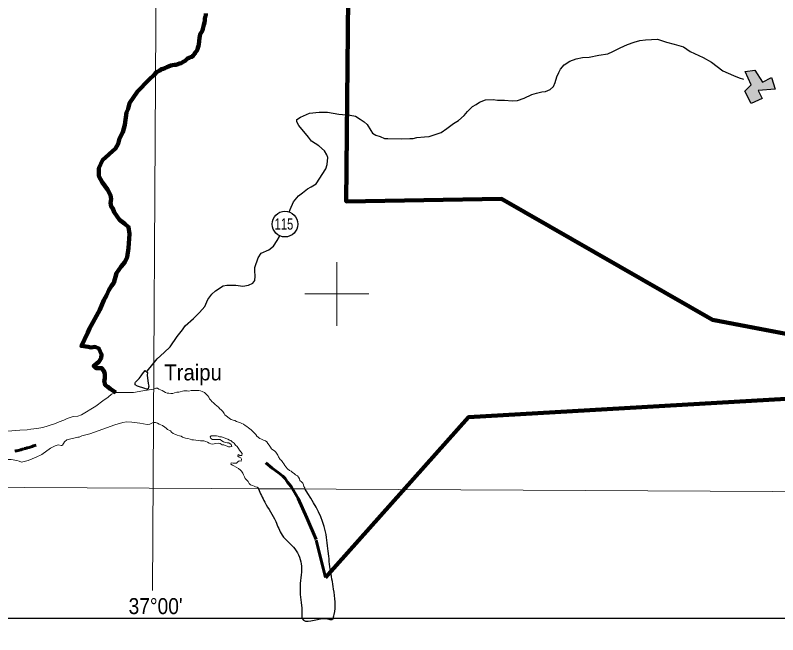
# Model space of a CAD drawing. Extents: x -1643653 to 4543381, y 1624270 to 13878484.
# Drawn here: x 714916 to 738822, y 8889327 to 8908730 of the extents above; entities that cross this region are included whole.
import ezdxf
from ezdxf.enums import TextEntityAlignment as Align

# ---------------------------------------------------------------- set-up
doc = ezdxf.new("R2010")
doc.units = 0
doc.header["$LTSCALE"] = 200
doc.linetypes.add('LONG_DASH_SHORT_DASH', pattern=[9.9, 6, -1.2, 1.5, -1.2])
for name, color, linetype, lineweight in [('1', 7, 'Continuous', 13), ('12', 7, 'Continuous', 25), ('2', 7, 'Continuous', 13), ('21', 7, 'Continuous', 25), ('24', 7, 'Continuous', 25), ('25', 7, 'Continuous', 13), ('3', 7, 'Continuous', 13), ('48', 7, 'Continuous', 25), ('53', 7, 'Continuous', 106), ('60', 7, 'Continuous', 13), ('7', 7, 'LONG_DASH_SHORT_DASH', 60), ('9', 7, 'Continuous', 90)]:
    doc.layers.add(name, color=color, linetype=linetype, lineweight=lineweight)
doc.layers.add('41', color=7, linetype='Continuous')
doc.layers.add('46', color=7, linetype='Continuous')

msp = doc.modelspace()

# ---------------------------------------------------------------- hatches: boundary and pattern name
at = {"layer": '21'}
msp.add_hatch(color=256, dxfattribs=at).paths.add_polyline_path([(737801.5, 8906970.9), (738106.6, 8907012.5), (738347.6, 8906633.5), (738630.7, 8906778.2), (738745.6, 8906416), (738212.5, 8906368.9), (738331.1, 8906121.9), (737984.3, 8905966.4), (737794.3, 8906356.6), (737990.6, 8906555.2)])

# ---------------------------------------------------------------- linework, layer by layer
at = {"layer": '1'}
for points in [[(719978.9, 9023574.5), (719561.6, 8949232.2), (719215.6, 8890710.6)], [(564751.7, 8894587.5), (664411.9, 8894209.9), (791388.5, 8893536.2)]]:
    msp.add_lwpolyline(points, dxfattribs=at)
at = {"layer": '12'}
for points in [[(732698.6, 8907406), (732912.6, 8907415.8), (733208.3, 8907476.3), (733493.7, 8907526.8), (733646.8, 8907597.8), (733881.6, 8907714.5), (734106.1, 8907810.9), (734320.4, 8907892), (734498.8, 8907937.5), (734677.2, 8907962.7), (734865.7, 8907967.4), (735054.3, 8907977.3), (735334.1, 8907885.1), (735578.4, 8907823.5), (735863.4, 8907741.4), (736076.8, 8907598.4), (736483.7, 8907404.1), (736742.9, 8907255.9), (737103.6, 8906990.3), (737439.3, 8906842), (737612.3, 8906775.4), (737750.2, 8906727.3)], [(727039.6, 8904864.2), (727284.1, 8904868.9), (727391.1, 8904868.7), (727508.4, 8904899), (727747.9, 8904919), (727890.6, 8904928.9), (728048.7, 8904984.6), (728268, 8905055.5), (728451.9, 8905187.7), (728651.2, 8905340.1), (728809.4, 8905436.6), (728993.4, 8905594.2), (729095.8, 8905716.2), (729249.1, 8905868.8), (729371.7, 8905934.8), (729473.8, 8906011), (729657.5, 8906082), (729896.9, 8906091.7), (730039.5, 8906071.1), (730253.5, 8906065.6), (730497.9, 8906055), (730661, 8906064.9), (730870.1, 8906130.7), (731110, 8906247.4), (731263, 8906293), (731426.1, 8906328.3), (731543.3, 8906338.3), (731686.2, 8906409.4), (731788.5, 8906500.9), (731839.8, 8906623.1), (731891.5, 8906806.3), (731958.2, 8906938.7), (732014.6, 8907040.4), (732122.1, 8907172.7), (732300.8, 8907289.5), (732499.7, 8907365.6), (732698.6, 8907406)], [(723502.8, 8902567), (723531.6, 8902649.7), (723639.5, 8902883.8), (723793, 8903072), (723920.7, 8903168.5), (724079.1, 8903290.5), (724191.4, 8903356.5), (724349.7, 8903453), (724652, 8903916), (724698.3, 8904058.6), (724714.4, 8904272.5), (724689.2, 8904354.1), (724613.3, 8904481.5), (724430.5, 8904644.9), (724201.8, 8904787.9), (724110.5, 8904915.5), (723811.3, 8905272.6), (723745.5, 8905389.9), (723740.7, 8905461.2), (723858.1, 8905542.5), (724143.8, 8905659.1), (724444.6, 8905699.3), (724704.4, 8905698.9), (725060.7, 8905637.1), (725417.2, 8905595.7), (725585.2, 8905564.8), (725732.6, 8905477.9), (725859.7, 8905396.2), (725945.9, 8905304.3), (726062.4, 8905115.6), (726113.1, 8905039.1), (726219.8, 8904977.8), (726352.1, 8904931.7), (726489.4, 8904870.3), (726601.5, 8904865), (727039.6, 8904864.2)], [(719051.7, 8897586.9), (719362.5, 8897965.7), (719587.4, 8898163.9), (719771.5, 8898341.9), (719996.8, 8898667.5), (720160.6, 8898881.1), (720247.7, 8899003.2), (720508.3, 8899237.1), (720697.5, 8899420.1), (720856.1, 8899608.3), (720953.7, 8899827.2), (721076.6, 8899989.9), (721194.2, 8900101.8), (721434.2, 8900254.2), (721551.4, 8900279.4), (721826.5, 8900273.8), (722050.5, 8900248), (722223.9, 8900278.2), (722366.7, 8900339.1), (722428.2, 8900425.6), (722433.7, 8900552.9), (722424.2, 8900726.1), (722429.7, 8900828), (722532.7, 8901133.4), (722624.9, 8901275.9), (722864.7, 8901387.5), (723007.8, 8901494.2), (723130.7, 8901677.4), (723197.4, 8901799.6), (723209.3, 8901823.1)]]:
    msp.add_lwpolyline(points, dxfattribs=at)
at = {"layer": '2'}
for p, q in [((725000, 8899000), (725000, 8901000)), ((724000, 8900000), (726000, 8900000))]:
    msp.add_line(p, q, dxfattribs=at)
at = {"layer": '21'}
for points in [[(737801.5, 8906970.9), (738106.6, 8907012.5), (738347.6, 8906633.5), (738630.7, 8906778.2), (738745.6, 8906416), (738212.5, 8906368.9), (738331.1, 8906121.9), (737984.3, 8905966.4), (737794.3, 8906356.6), (737990.6, 8906555.2)], [(718993.1, 8897599.9), (719057.4, 8897544.6), (719055.9, 8897461.4), (719085.3, 8897192.5), (719103.1, 8897108.8), (719098.1, 8897076.1), (719079.4, 8897033), (719065.5, 8897020), (719028.2, 8897020.1), (718974.7, 8897034.1), (718746.2, 8897111.7), (718679.7, 8897153.1), (718671.6, 8897221.2), (718685, 8897240.1), (718799.2, 8897348.2), (718862.4, 8897430.9), (718906.6, 8897502.9)]]:
    msp.add_lwpolyline(points, close=True, dxfattribs=at)
at = {"layer": '24', "lineweight": 53}
for points in [[(720886.9, 8908780.4), (720886.5, 8908724.4), (720865.8, 8908678.7), (720860.4, 8908622.7), (720854.9, 8908561.6), (720844.3, 8908500.6), (720828.6, 8908434.4), (720818, 8908383.6), (720797.2, 8908307.3), (720781.6, 8908256.4), (720750.7, 8908200.6), (720714.6, 8908139.7), (720699, 8908078.7), (720693.5, 8908027.8), (720680.1, 8907917.9)], [(720680.1, 8907917.9), (720671.8, 8907819.1), (720661.2, 8907768.2), (720640.5, 8907712.3), (720624.9, 8907661.5), (720594, 8907605.6), (720558.1, 8907560), (720532.3, 8907509.3), (720496.4, 8907468.7), (720460.5, 8907428.2), (720409.6, 8907413.3), (720363.7, 8907393.2), (720312.7, 8907373.1), (720276.8, 8907337.7), (720241, 8907302.3), (720179.7, 8907267), (720118.4, 8907231.8), (720062.3, 8907216.8), (720016.4, 8907196.8), (719965.5, 8907181.8), (719909.5, 8907177.1), (719843.3, 8907162.2), (719792.3, 8907152.3), (719720.9, 8907122.2), (719664.9, 8907107.3), (719603.6, 8907077.1), (719552.6, 8907057.1), (719496.6, 8907042.2), (719445.4, 8907001.8), (719343.4, 8906951.5), (719283.6, 8906877)], [(719283.6, 8906877), (719100.8, 8906711), (718751.9, 8906345.6), (718502.7, 8905980.3), (718452.8, 8905797.7), (718403, 8905681.4), (718353.1, 8905299.5), (718286.7, 8905067), (718187, 8904867.8), (718137.2, 8904701.7), (718054.1, 8904552.2), (717859.9, 8904374.3), (717854.7, 8904369.6)], [(717854.7, 8904369.6), (717655.3, 8904186.9), (717539, 8903937.8), (717539, 8903688.8), (717638.7, 8903506.1), (717804.9, 8903273.6), (717904.6, 8903091), (717921.2, 8902974.7), (717904.6, 8902858.5), (717921.2, 8902742.3), (717971.1, 8902675.9), (718020.9, 8902559.6), (718187, 8902327.1), (718353.2, 8902194.3), (718469.5, 8902094.7), (718502.7, 8901878.8), (718469.5, 8901430.4), (718419.6, 8901148.2), (718353.2, 8900998.7), (718236.8, 8900865.9), (718087.3, 8900650), (718004.2, 8900351.1), (717937.8, 8900251.5), (717854.7, 8900118.6), (717771.7, 8899952.6), (717688.6, 8899803.1), (717572.3, 8899504.2), (717240, 8898923), (717190.1, 8898790.2), (717090.4, 8898574.3), (716990.8, 8898375.1), (717206.8, 8898341.9), (717289.8, 8898325.2), (717422.7, 8898341.9), (717539, 8898292), (717622.1, 8898109.4), (717605.5, 8897993.1), (717539, 8897876.9), (717472.6, 8897827.1), (717422.7, 8897777.3), (717372.9, 8897744.1), (717439.4, 8897677.6), (717622.1, 8897677.6), (717688.6, 8897594.6), (717721.8, 8897495), (717721.8, 8897395.3), (717721.8, 8897345.5), (717705.2, 8897279.1), (717721.8, 8897196.1), (717738.4, 8897146.3), (717821.5, 8897096.4), (717888, 8897030), (718070.7, 8896913.8)]]:
    msp.add_lwpolyline(points, dxfattribs=at)
at = {"layer": '25', "lineweight": 25}
msp.add_line((724002.8, 8893886.5), (722537.3, 8893896.5), dxfattribs=at)
msp.add_line((724002.8, 8893886.5), (722537.3, 8893896.5), dxfattribs=at)
at = {"layer": '25'}
for points in [[(716671.9, 8896141.4), (716736, 8896160), (716876.8, 8896172.9), (716996.8, 8896216.3), (717443.2, 8896481.3), (717658.9, 8896651.8), (717833.2, 8896772.8), (717934, 8896865.6), (718070.7, 8896913.8), (718220.3, 8896913.8), (718619, 8896913.8), (718918.1, 8896963.6), (719252.2, 8897020.3)], [(719252.2, 8897020.3), (719320.1, 8897049.2), (719376, 8897048.8), (719416.5, 8897018), (719467.2, 8896997.3), (719517.9, 8896971.5), (719578.7, 8896940.5), (719624.3, 8896914.8), (719680.1, 8896894), (719736.1, 8896888.6), (719797.1, 8896883.1), (719858.1, 8896887.8), (719909.1, 8896907.8), (719980.4, 8896922.7), (720046.6, 8896927.3), (720199.4, 8896962), (720255.3, 8896961.7), (720306.2, 8896961.3), (720362.2, 8896961), (720428.4, 8896980.9), (720479.3, 8896980.6), (720540.3, 8896980.2), (720606.4, 8896979.8), (720667.5, 8896979.4), (720723.3, 8896968.8), (720779.1, 8896948.1), (720845, 8896917.1), (720880.4, 8896881.2), (720920.8, 8896845.3), (720956.2, 8896809.4)], [(720956.2, 8896809.4), (720981.3, 8896763.4), (721006.4, 8896717.4), (721046.8, 8896676.4), (721082.2, 8896635.4), (721127.7, 8896594.4), (721188.3, 8896538), (721289.5, 8896455.8), (721329.8, 8896404.6), (721375.3, 8896368.7), (721420.8, 8896322.5), (721461, 8896261.2), (721486.2, 8896215.2), (721567.1, 8896148.4), (721627.8, 8896097.1), (721683.5, 8896071.3), (721749.5, 8896050.5), (721805.3, 8896034.8), (721856, 8896009), (721916.9, 8895988.3), (721972.7, 8895967.5), (722018.4, 8895946.9), (722069, 8895921.1), (722119.7, 8895885.1), (722175.4, 8895854.2), (722231, 8895808), (722271.5, 8895772), (722312, 8895741.2), (722367.5, 8895689.9), (722402.9, 8895654), (722463.5, 8895597.6), (722493.7, 8895546.5), (722584.8, 8895474.6), (722635.5, 8895453.9), (722701.4, 8895417.8), (722762.3, 8895402.1), (722802.7, 8895366.2), (722832.9, 8895320.2), (722873.2, 8895263.9), (722923.6, 8895197.3), (722953.8, 8895151.3), (722994.3, 8895120.5), (723039.9, 8895089.6), (723085.4, 8895048.6), (723145.7, 8894951.4), (723165.7, 8894895.3), (723221.1, 8894818.5), (723261.6, 8894782.6), (723301.9, 8894726.3), (723337.1, 8894675.1), (723367.3, 8894624), (723402.6, 8894583), (723453.1, 8894526.7), (723518.8, 8894475.3), (723564.4, 8894449.5), (723609.9, 8894408.5), (723655.5, 8894372.5), (723706.1, 8894336.6), (723761.8, 8894305.6), (723797.1, 8894259.6), (723827.3, 8894208.4), (723842.2, 8894157.4), (723887.6, 8894111.3), (723928.1, 8894075.3), (723948, 8894019.2)], [(715944.9, 8895871), (716177.3, 8895944.3), (716297, 8895998.6), (716434.9, 8896046.3), (716544.4, 8896104.3), (716671.9, 8896141.4)], [(715407.8, 8895761.9), (715591.5, 8895783.2), (715777.5, 8895818.2), (715944.9, 8895871)], [(719242.1, 8895974.6), (719137.8, 8895926.7), (719051.9, 8895910.8), (718819, 8895950.7), (718570.6, 8895982.3), (718406.7, 8895992.1), (718284.1, 8895976.8), (718038.4, 8895905.8), (717250.7, 8895623.3), (716998.4, 8895554.6), (716915, 8895518.1), (716881.8, 8895513.8)], [(721516.7, 8895476.3), (721445.7, 8895507.4), (721379.7, 8895523.1), (721323.7, 8895523.4), (721273, 8895544.1), (721222.2, 8895559.7), (721151.1, 8895560.2), (721054.4, 8895560.8), (721023.6, 8895520.3), (721043.6, 8895469.2), (721104.5, 8895443.3), (721160.4, 8895443), (721211.3, 8895442.7), (721277.4, 8895442.2), (721343.5, 8895436.7), (721394.1, 8895395.6), (721444.7, 8895364.7), (721505.6, 8895344), (721561.5, 8895338.5), (721612.4, 8895338.2), (721688.3, 8895286.8), (721708.2, 8895225.5), (721657.3, 8895210.6), (721606.4, 8895210.9), (721555.7, 8895231.6), (721499.9, 8895252.3), (721454.2, 8895273), (721398.3, 8895278.4), (721342.7, 8895319.6), (721276.6, 8895325.1), (721205.3, 8895320.4), (721154.4, 8895305.5), (721098.4, 8895300.7), (721042.5, 8895301.1), (720996.9, 8895326.9), (720941.1, 8895357.8), (720890.4, 8895378.5), (720824.4, 8895399.3), (720773.6, 8895399.6), (720722.7, 8895399.9), (720656.6, 8895405.4), (720580.4, 8895421.2), (720509.3, 8895426.8), (720448.2, 8895427.2), (720397.5, 8895447.9), (720326.5, 8895468.7), (720250.3, 8895484.5), (720158.9, 8895515.6), (720113.3, 8895541.4), (720062.6, 8895557), (719996.6, 8895577.8), (719920.5, 8895608.8), (719864.8, 8895634.7), (719819.3, 8895675.7), (719778.8, 8895711.6), (719692.7, 8895758), (719647.2, 8895799.1), (719606.7, 8895829.9), (719535.8, 8895876.2), (719480.1, 8895902), (719429.3, 8895917.6), (719373.6, 8895948.5), (719317.8, 8895969.3), (719266.9, 8895969.6), (719242.1, 8895974.6)], [(714514.6, 8895674.6), (714664.7, 8895703.8), (714810.4, 8895708.8), (715055.3, 8895739.1), (715289.1, 8895748.2), (715407.8, 8895761.9)], [(716881.8, 8895513.8), (716841.2, 8895508.6), (716533, 8895427), (716458.2, 8895365.9), (716394.5, 8895260), (716374.9, 8895256.9)], [(722073.4, 8894336.8), (722053.4, 8894382.8), (722013.2, 8894449.3), (721972.7, 8894485.2), (721917.1, 8894531.4), (721846.2, 8894572.6), (721770.2, 8894618.9), (721724.6, 8894639.6), (721673.9, 8894665.4), (721689.5, 8894716.2), (721745.3, 8894700.6), (721801.3, 8894700.2), (721852.2, 8894705), (721893.1, 8894740.4), (721934, 8894770.7), (721995, 8894765.2), (722010.6, 8894821.2), (721985.5, 8894867.2), (721934.8, 8894893), (721889.3, 8894923.8), (721909.9, 8894969.5), (721960.6, 8894943.7), (722021.6, 8894943.3), (722027.1, 8895004.4), (721986.8, 8895050.5), (721946.5, 8895106.8), (721911.2, 8895163.1), (721871, 8895219.4), (721825.5, 8895260.4), (721780.1, 8895321.8), (721719.4, 8895368.1), (721679, 8895409.1), (721628.2, 8895424.7), (721577.6, 8895455.6), (721516.7, 8895476.3)], [(715039.1, 8894760), (714963.6, 8894786.5), (714790.6, 8894820), (714606.1, 8894818.8), (714473.2, 8894853.3), (714404.1, 8894859.6), (714116.9, 8894843.6), (714034.5, 8894876.8), (713967, 8894916.7), (713850.5, 8895013.2), (713789.1, 8895053.9), (713604, 8895144.8), (713532.7, 8895186.2)], [(716374.9, 8895256.9), (716350.2, 8895253.1), (716257.5, 8895274.6), (716162.3, 8895243), (716023.3, 8895172.8), (715744.1, 8894976.4), (715570.5, 8894886.6), (715322, 8894784.1), (715114.6, 8894733.5), (715039.1, 8894760)], [(722537.3, 8893896.5), (722543.5, 8893916.1), (722503.1, 8893952.1), (722447.2, 8893962.6), (722401.6, 8893983.3), (722350.9, 8894004), (722295.1, 8894024.7), (722244.5, 8894065.8), (722214.3, 8894122), (722174, 8894168.1), (722128.6, 8894224.4), (722098.4, 8894270.5), (722073.4, 8894336.8)], [(723948, 8894019.2), (723962.9, 8893968.2), (723993.2, 8893927.2), (724002.8, 8893886.5), (722537.3, 8893896.5)]]:
    msp.add_lwpolyline(points, dxfattribs=at)
at = {"layer": '25', "lineweight": 25}
for points in [[(722537.3, 8893896.5), (722740.6, 8893475.5), (723084.4, 8892873.8), (723285, 8892444), (723686.1, 8892014.3), (723886.7, 8891469.9), (723843.7, 8890753.6), (723901, 8890080.3), (723900.8, 8889934.8), (723915.3, 8889836.7), (724574.3, 8889836.7), (724631.6, 8889836.7), (724883.2, 8889836.5), (724893.2, 8889883.7), (724911.8, 8889958.1), (724898, 8890758.3), (724794.3, 8891380.3), (724717.6, 8892028.6), (724603, 8892716.2), (724002.8, 8893886.5)], [(722537.3, 8893896.5), (722740.6, 8893475.5), (723084.4, 8892873.8), (723285, 8892444), (723686.1, 8892014.3), (723886.7, 8891469.9), (723843.7, 8890753.6), (723901, 8890080.3), (723901.3, 8889998.4)], [(724811.6, 8891262.3), (724794.3, 8891380.3), (724717.6, 8892028.6), (724603, 8892716.2), (724002.8, 8893886.5)]]:
    msp.add_spline(points, degree=3, dxfattribs=at)
at = {"layer": '3', "lineweight": 25}
msp.add_lwpolyline([(563033.9, 9026438.8), (793061.1, 9026438.8), (793495.6, 8889836.8), (563468.3, 8889836.8)], close=True, dxfattribs=at)
at = {"layer": '48'}
msp.add_circle((723371.8, 8902188.1), 401.3, dxfattribs=at)
at = {"layer": '53'}
for points in [[(720886.9, 8908780.4), (720886.5, 8908724.4), (720865.8, 8908678.7), (720860.4, 8908622.7), (720854.9, 8908561.6), (720844.3, 8908500.6), (720828.6, 8908434.4), (720818, 8908383.6), (720797.2, 8908307.3), (720781.6, 8908256.4), (720750.7, 8908200.6), (720714.6, 8908139.7), (720699, 8908078.7), (720693.5, 8908027.8), (720680.1, 8907917.9)], [(720886.9, 8908780.4), (720886.5, 8908724.4), (720865.8, 8908678.7), (720860.4, 8908622.7), (720854.9, 8908561.6), (720844.3, 8908500.6), (720828.6, 8908434.4), (720818, 8908383.6), (720797.2, 8908307.3), (720781.6, 8908256.4), (720750.7, 8908200.6), (720714.6, 8908139.7), (720699, 8908078.7), (720693.5, 8908027.8), (720680.1, 8907917.9)], [(720886.9, 8908780.4), (720886.5, 8908724.4), (720865.8, 8908678.7), (720860.4, 8908622.7), (720854.9, 8908561.6), (720844.3, 8908500.6), (720828.6, 8908434.4), (720818, 8908383.6), (720797.2, 8908307.3), (720781.6, 8908256.4), (720750.7, 8908200.6), (720714.6, 8908139.7), (720699, 8908078.7), (720693.5, 8908027.8), (720680.1, 8907917.9)], [(720680.1, 8907917.9), (720671.8, 8907819.1), (720661.2, 8907768.2), (720640.5, 8907712.3), (720624.9, 8907661.5), (720594, 8907605.6), (720558.1, 8907560), (720532.3, 8907509.3), (720496.4, 8907468.7), (720460.5, 8907428.2), (720409.6, 8907413.3), (720363.7, 8907393.2), (720312.7, 8907373.1), (720276.8, 8907337.7), (720241, 8907302.3), (720179.7, 8907267), (720118.4, 8907231.8), (720062.3, 8907216.8), (720016.4, 8907196.8), (719965.5, 8907181.8), (719909.5, 8907177.1), (719843.3, 8907162.2), (719792.3, 8907152.3), (719720.9, 8907122.2), (719664.9, 8907107.3), (719603.6, 8907077.1), (719552.6, 8907057.1), (719496.6, 8907042.2), (719445.4, 8907001.8), (719343.4, 8906951.5), (719283.6, 8906877)], [(720680.1, 8907917.9), (720671.8, 8907819.1), (720661.2, 8907768.2), (720640.5, 8907712.3), (720624.9, 8907661.5), (720594, 8907605.6), (720558.1, 8907560), (720532.3, 8907509.3), (720496.4, 8907468.7), (720460.5, 8907428.2), (720409.6, 8907413.3), (720363.7, 8907393.2), (720312.7, 8907373.1), (720276.8, 8907337.7), (720241, 8907302.3), (720179.7, 8907267), (720118.4, 8907231.8), (720062.3, 8907216.8), (720016.4, 8907196.8), (719965.5, 8907181.8), (719909.5, 8907177.1), (719843.3, 8907162.2), (719792.3, 8907152.3), (719720.9, 8907122.2), (719664.9, 8907107.3), (719603.6, 8907077.1), (719552.6, 8907057.1), (719496.6, 8907042.2), (719445.4, 8907001.8), (719343.4, 8906951.5), (719283.6, 8906877)], [(720680.1, 8907917.9), (720671.8, 8907819.1), (720661.2, 8907768.2), (720640.5, 8907712.3), (720624.9, 8907661.5), (720594, 8907605.6), (720558.1, 8907560), (720532.3, 8907509.3), (720496.4, 8907468.7), (720460.5, 8907428.2), (720409.6, 8907413.3), (720363.7, 8907393.2), (720312.7, 8907373.1), (720276.8, 8907337.7), (720241, 8907302.3), (720179.7, 8907267), (720118.4, 8907231.8), (720062.3, 8907216.8), (720016.4, 8907196.8), (719965.5, 8907181.8), (719909.5, 8907177.1), (719843.3, 8907162.2), (719792.3, 8907152.3), (719720.9, 8907122.2), (719664.9, 8907107.3), (719603.6, 8907077.1), (719552.6, 8907057.1), (719496.6, 8907042.2), (719445.4, 8907001.8), (719343.4, 8906951.5), (719283.6, 8906877)], [(719283.6, 8906877), (719100.8, 8906711), (718751.9, 8906345.6), (718502.7, 8905980.3), (718452.8, 8905797.7), (718403, 8905681.4), (718353.1, 8905299.5), (718286.7, 8905067), (718187, 8904867.8), (718137.2, 8904701.7), (718054.1, 8904552.2), (717859.9, 8904374.3), (717854.7, 8904369.6)], [(719283.6, 8906877), (719100.8, 8906711), (718751.9, 8906345.6), (718502.7, 8905980.3), (718452.8, 8905797.7), (718403, 8905681.4), (718353.1, 8905299.5), (718286.7, 8905067), (718187, 8904867.8), (718137.2, 8904701.7), (718054.1, 8904552.2), (717859.9, 8904374.3), (717854.7, 8904369.6)], [(719283.6, 8906877), (719100.8, 8906711), (718751.9, 8906345.6), (718502.7, 8905980.3), (718452.8, 8905797.7), (718403, 8905681.4), (718353.1, 8905299.5), (718286.7, 8905067), (718187, 8904867.8), (718137.2, 8904701.7), (718054.1, 8904552.2), (717859.9, 8904374.3), (717854.7, 8904369.6)], [(717854.7, 8904369.6), (717655.3, 8904186.9), (717539, 8903937.8), (717539, 8903688.8), (717638.7, 8903506.1), (717804.9, 8903273.6), (717904.6, 8903091), (717921.2, 8902974.7), (717904.6, 8902858.5), (717921.2, 8902742.3), (717971.1, 8902675.9), (718020.9, 8902559.6), (718187, 8902327.1), (718353.2, 8902194.3), (718469.5, 8902094.7), (718502.7, 8901878.8), (718469.5, 8901430.4), (718419.6, 8901148.2), (718353.2, 8900998.7), (718236.8, 8900865.9), (718087.3, 8900650), (718004.2, 8900351.1), (717937.8, 8900251.5), (717854.7, 8900118.6), (717771.7, 8899952.6), (717688.6, 8899803.1), (717572.3, 8899504.2), (717240, 8898923), (717190.1, 8898790.2), (717090.4, 8898574.3), (716990.8, 8898375.1), (717206.8, 8898341.9), (717289.8, 8898325.2), (717422.7, 8898341.9), (717539, 8898292), (717622.1, 8898109.4), (717605.5, 8897993.1), (717539, 8897876.9), (717472.6, 8897827.1), (717422.7, 8897777.3), (717372.9, 8897744.1), (717439.4, 8897677.6), (717622.1, 8897677.6), (717688.6, 8897594.6), (717721.8, 8897495), (717721.8, 8897395.3), (717721.8, 8897345.5), (717705.2, 8897279.1), (717721.8, 8897196.1), (717738.4, 8897146.3), (717821.5, 8897096.4), (717888, 8897030), (718070.7, 8896913.8)], [(717854.7, 8904369.6), (717655.3, 8904186.9), (717539, 8903937.8), (717539, 8903688.8), (717638.7, 8903506.1), (717804.9, 8903273.6), (717904.6, 8903091), (717921.2, 8902974.7), (717904.6, 8902858.5), (717921.2, 8902742.3), (717971.1, 8902675.9), (718020.9, 8902559.6), (718187, 8902327.1), (718353.2, 8902194.3), (718469.5, 8902094.7), (718502.7, 8901878.8), (718469.5, 8901430.4), (718419.6, 8901148.2), (718353.2, 8900998.7), (718236.8, 8900865.9), (718087.3, 8900650), (718004.2, 8900351.1), (717937.8, 8900251.5), (717854.7, 8900118.6), (717771.7, 8899952.6), (717688.6, 8899803.1), (717572.3, 8899504.2), (717240, 8898923), (717190.1, 8898790.2), (717090.4, 8898574.3), (716990.8, 8898375.1), (717206.8, 8898341.9), (717289.8, 8898325.2), (717422.7, 8898341.9), (717539, 8898292), (717622.1, 8898109.4), (717605.5, 8897993.1), (717539, 8897876.9), (717472.6, 8897827.1), (717422.7, 8897777.3), (717372.9, 8897744.1), (717439.4, 8897677.6), (717622.1, 8897677.6), (717688.6, 8897594.6), (717721.8, 8897495), (717721.8, 8897395.3), (717721.8, 8897345.5), (717705.2, 8897279.1), (717721.8, 8897196.1), (717738.4, 8897146.3), (717821.5, 8897096.4), (717888, 8897030), (718070.7, 8896913.8)], [(717854.7, 8904369.6), (717655.3, 8904186.9), (717539, 8903937.8), (717539, 8903688.8), (717638.7, 8903506.1), (717804.9, 8903273.6), (717904.6, 8903091), (717921.2, 8902974.7), (717904.6, 8902858.5), (717921.2, 8902742.3), (717971.1, 8902675.9), (718020.9, 8902559.6), (718187, 8902327.1), (718353.2, 8902194.3), (718469.5, 8902094.7), (718502.7, 8901878.8), (718469.5, 8901430.4), (718419.6, 8901148.2), (718353.2, 8900998.7), (718236.8, 8900865.9), (718087.3, 8900650), (718004.2, 8900351.1), (717937.8, 8900251.5), (717854.7, 8900118.6), (717771.7, 8899952.6), (717688.6, 8899803.1), (717572.3, 8899504.2), (717240, 8898923), (717190.1, 8898790.2), (717090.4, 8898574.3), (716990.8, 8898375.1), (717206.8, 8898341.9), (717289.8, 8898325.2), (717422.7, 8898341.9), (717539, 8898292), (717622.1, 8898109.4), (717605.5, 8897993.1), (717539, 8897876.9), (717472.6, 8897827.1), (717422.7, 8897777.3), (717372.9, 8897744.1), (717439.4, 8897677.6), (717622.1, 8897677.6), (717688.6, 8897594.6), (717721.8, 8897495), (717721.8, 8897395.3), (717721.8, 8897345.5), (717705.2, 8897279.1), (717721.8, 8897196.1), (717738.4, 8897146.3), (717821.5, 8897096.4), (717888, 8897030), (718070.7, 8896913.8)]]:
    msp.add_lwpolyline(points, dxfattribs=at)
at = {"layer": '60', "lineweight": 25}
msp.add_spline([(814781, 9009175.5), (814787.2, 9009173.4), (814796.9, 9009173.4), (814799.4, 9009172.4), (814805.1, 9009174.5), (814805.6, 9009176.5), (814811.7, 9009179.5), (814811.7, 9009179.5), (814801.5, 9009181), (814790.7, 9009181.5), (814784.1, 9009183.1), (814777.4, 9009185.1), (814778.4, 9009175.5)], degree=3, dxfattribs=at)
at = {"layer": '7'}
for points in [[(715172.3, 8895138.8), (715134.1, 8895136.3), (715085.8, 8895115.8), (715047.6, 8895103.1), (715004.4, 8895095.4), (714963.7, 8895087.7), (714935.7, 8895082.6), (714900.1, 8895077.5)], [(715575.1, 8895269.4), (715574.3, 8895269.2), (715533.6, 8895253.9), (715487.8, 8895238.5), (715444.5, 8895225.8), (715347.8, 8895195.1), (715294.4, 8895177.2), (715248.6, 8895164.4), (715200.3, 8895159.3), (715172.3, 8895138.8)], [(724638.9, 8891123.6), (724349.6, 8892305.9), (724059.6, 8892992.2), (723788.9, 8893591.5), (723566.6, 8893968.5), (723450.6, 8894103.8), (723373.3, 8894219.2), (723307.3, 8894290.7), (723154.9, 8894408.1), (722972, 8894546), (722773.8, 8894710.7)]]:
    msp.add_lwpolyline(points, dxfattribs=at)
at = {"layer": '9'}
msp.add_line((741371.9, 8898310.2), (736775.3, 8899194.4), dxfattribs=at)
for points in [[(741371.9, 8898310.2), (736775.3, 8899194.4), (730163.4, 8902976.8), (725291.2, 8902898), (725401.2, 8914588.3), (719613.1, 8922670.1)], [(724638.9, 8891123.6), (729122.2, 8896139.1), (740717.5, 8896813.6), (741371.9, 8898310.2)]]:
    msp.add_lwpolyline(points, dxfattribs=at)

# ---------------------------------------------------------------- texts
at = {"layer": '41', "width": 0.95}
msp.add_text('Traipu', height=500, dxfattribs=at).set_placement((719591.1, 8897292.6))
at = {"layer": '46', "width": 0.9}
msp.add_text("37°00'", height=500, dxfattribs=at).set_placement((719315, 8889973.1), align=Align.CENTER)
at = {"layer": '48', "width": 0.75}
msp.add_text('115', height=350, dxfattribs=at).set_placement((723340.2, 8902014.7), align=Align.CENTER)

doc.saveas('drawing.dxf')
